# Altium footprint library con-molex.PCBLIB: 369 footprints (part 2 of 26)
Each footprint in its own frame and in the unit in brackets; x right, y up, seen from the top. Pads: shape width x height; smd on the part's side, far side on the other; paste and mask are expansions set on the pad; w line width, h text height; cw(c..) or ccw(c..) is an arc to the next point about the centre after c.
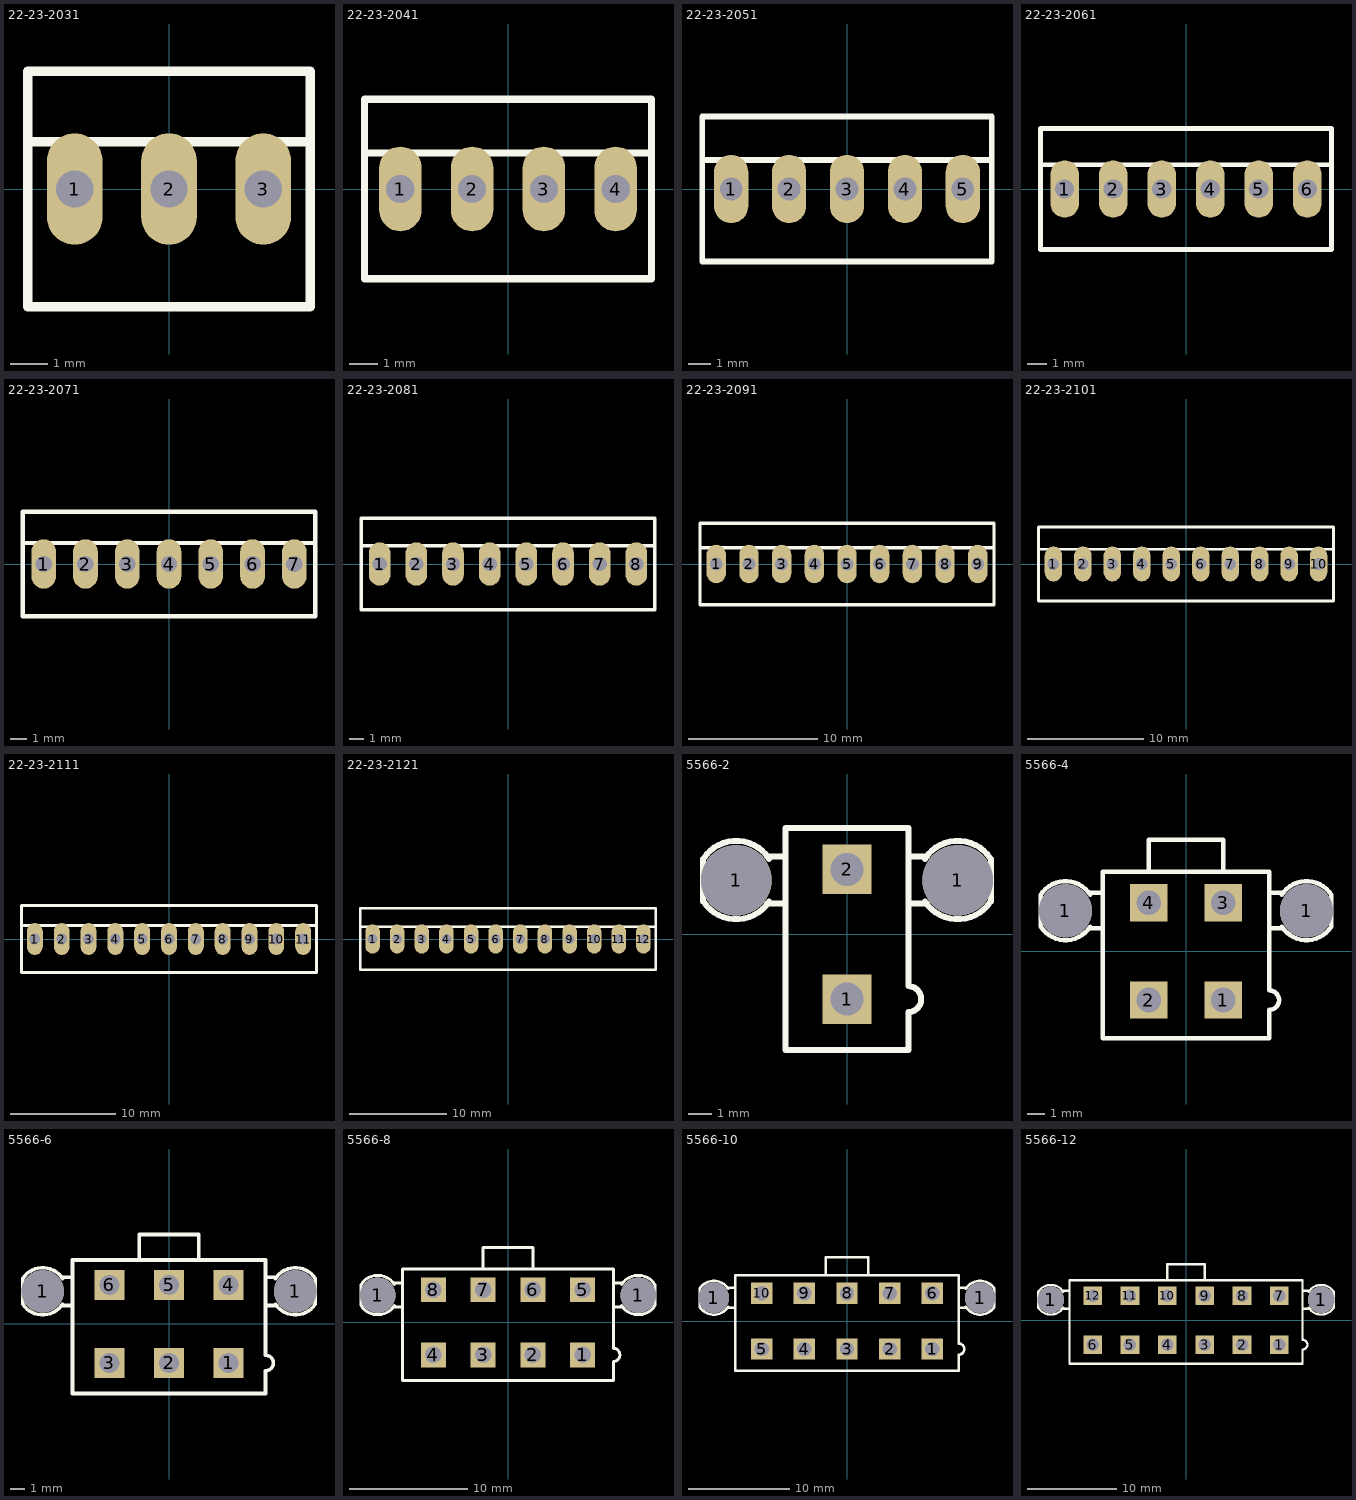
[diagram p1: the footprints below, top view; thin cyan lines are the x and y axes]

## 22-23-2031 [mm]
pads (3):
  oval 1.5x3 hole 1: 1(-2.54,0) 2(0,0) 3(2.54,0)
Top Overlay:
  lines w0.254: -3.81,1.27 -3.81,-3.175 3.81,-3.175 3.81,1.27 ; -3.81,1.27 -3.81,3.175 3.81,3.175 3.81,1.27 ; -3.81,1.27 3.81,1.27

## 22-23-2041 [mm]
pads (4):
  oval 1.5x3 hole 1: 1(-3.81,0) 2(-1.27,0) 3(1.27,0) 4(3.81,0)
Top Overlay:
  lines w0.254: -5.08,1.27 -5.08,-3.175 5.08,-3.175 5.08,1.27 ; -5.08,1.27 -5.08,3.175 5.08,3.175 5.08,1.27 ; -5.08,1.27 5.08,1.27

## 22-23-2051 [mm]
pads (5):
  oval 1.5x3 hole 1: 1(-5.08,0) 2(-2.54,0) 3(0,0) 4(2.54,0) 5(5.08,0)
Top Overlay:
  lines w0.254: -6.35,1.27 -6.35,-3.175 6.35,-3.175 6.35,1.27 ; -6.35,1.27 -6.35,3.175 6.35,3.175 6.35,1.27 ; -6.35,1.27 6.35,1.27

## 22-23-2061 [mm]
pads (6):
  oval 1.5x3 hole 1: 1(-6.35,0) 2(-3.81,0) 3(-1.27,0) 4(1.27,0) 5(3.81,0) 6(6.35,0)
Top Overlay:
  lines w0.254: -7.62,1.27 -7.62,-3.175 7.62,-3.175 7.62,1.27 ; -7.62,1.27 -7.62,3.175 7.62,3.175 7.62,1.27 ; -7.62,1.27 7.62,1.27

## 22-23-2071 [mm]
pads (7):
  oval 1.5x3 hole 1: 1(-7.62,0) 2(-5.08,0) 3(-2.54,0) 4(0,0) 5(2.54,0) 6(5.08,0) 7(7.62,0)
Top Overlay:
  lines w0.254: -8.89,1.27 -8.89,-3.175 8.89,-3.175 8.89,1.27 ; -8.89,1.27 -8.89,3.175 8.89,3.175 8.89,1.27 ; -8.89,1.27 8.89,1.27

## 22-23-2081 [mm]
pads (8):
  oval 1.5x3 hole 1: 1(-8.89,0) 2(-6.35,0) 3(-3.81,0) 4(-1.27,0) 5(1.27,0) 6(3.81,0) 7(6.35,0) 8(8.89,0)
Top Overlay:
  lines w0.254: -10.16,1.27 -10.16,-3.175 10.16,-3.175 10.16,1.27 ; -10.16,1.27 -10.16,3.175 10.16,3.175 10.16,1.27 ; -10.16,1.27 10.16,1.27

## 22-23-2091 [mm]
pads (9):
  oval 1.5x3 hole 1: 1(-10.16,0) 2(-7.62,0) 3(-5.08,0) 4(-2.54,0) 5(0,0) 6(2.54,0) 7(5.08,0) 8(7.62,0) 9(10.16,0)
Top Overlay:
  lines w0.254: -11.43,1.27 -11.43,-3.175 11.43,-3.175 11.43,1.27 ; -11.43,1.27 -11.43,3.175 11.43,3.175 11.43,1.27 ; -11.43,1.27 11.43,1.27

## 22-23-2101 [mm]
pads (10):
  oval 1.5x3 hole 1: 1(-11.43,0) 2(-8.89,0) 3(-6.35,0) 4(-3.81,0) 5(-1.27,0) 6(1.27,0) 7(3.81,0) 8(6.35,0) 9(8.89,0) 10(11.43,0)
Top Overlay:
  lines w0.254: -12.7,1.27 -12.7,-3.175 12.7,-3.175 12.7,1.27 ; -12.7,1.27 -12.7,3.175 12.7,3.175 12.7,1.27 ; -12.7,1.27 12.7,1.27

## 22-23-2111 [mm]
pads (11):
  oval 1.5x3 hole 1: 1(-12.7,0) 2(-10.16,0) 3(-7.62,0) 4(-5.08,0) 5(-2.54,0) 6(0,0) 7(2.54,0) 8(5.08,0) 9(7.62,0) 10(10.16,0) 11(12.7,0)
Top Overlay:
  lines w0.254: -13.97,1.27 -13.97,-3.175 13.97,-3.175 13.97,1.27 ; -13.97,1.27 -13.97,3.175 13.97,3.175 13.97,1.27 ; -13.97,1.27 13.97,1.27

## 22-23-2121 [mm]
pads (12):
  oval 1.5x3 hole 1: 1(-13.97,0) 2(-11.43,0) 3(-8.89,0) 4(-6.35,0) 5(-3.81,0) 6(-1.27,0) 7(1.27,0) 8(3.81,0) 9(6.35,0) 10(8.89,0) 11(11.43,0) 12(13.97,0)
Top Overlay:
  lines w0.254: -15.24,1.27 -15.24,-3.175 15.24,-3.175 15.24,1.27 ; -15.24,1.27 -15.24,3.175 15.24,3.175 15.24,1.27 ; -15.24,1.27 15.24,1.27

## 5566-2 [mm]
pads (4):
  round 3 hole 3: 1(-4.7,2.29) 1(4.7,2.29)
  rect 2.1x2.1 hole 1.4: 1(0,-2.75) 2(0,2.75)
Top Overlay:
  lines w0.254: -3.4,1.3 -2.7,1.3 ; -3.4,3.3 -2.7,3.3 ; -3.3,1.4 cw(c-4.7,2.3) -6.1,1.4 -6.1,3.2 cw(c-4.7,2.3) -3.3,3.2 ; 2.7,1.3 3.4,1.3 ; 2.7,3.3 3.4,3.3 ; 3.3,1.4 ccw(c4.7,2.3) 6.1,1.4 6.1,3.2 ccw(c4.7,2.3) 3.3,3.2 ; -2.6,-4.9 -2.6,4.5 2.6,4.5 2.6,-2.2 cw(c2.6,-2.75) 2.6,-3.3 2.6,-4.9 -2.6,-4.9

## 5566-4 [mm]
pads (6):
  round 3 hole 3: 1(-6.8,2.29) 1(6.8,2.29)
  rect 2.1x2.1 hole 1.4: 1(2.1,-2.75) 2(-2.1,-2.75) 3(2.1,2.75) 4(-2.1,2.75)
Top Overlay:
  lines w0.254: -5.5,1.3 -4.8,1.3 ; -5.5,3.3 -4.8,3.3 ; -5.4,1.4 cw(c-6.8,2.3) -8.2,1.4 -8.2,3.2 cw(c-6.8,2.3) -5.4,3.2 ; -2.1,4.6 -2.1,6.3 2.1,6.3 2.1,4.6 ; 4.8,1.3 5.5,1.3 ; 4.8,3.3 5.5,3.3 ; 5.4,1.4 ccw(c6.8,2.3) 8.2,1.4 8.2,3.2 ccw(c6.8,2.3) 5.4,3.2 ; -4.7,-4.9 4.7,-4.9 4.7,-3.3 ccw(c4.7,-2.75) 4.7,-2.2 4.7,4.5 -4.7,4.5 -4.7,-4.9

## 5566-6 [mm]
pads (8):
  round 3 hole 3: 1(-8.9,2.29) 1(8.9,2.29)
  rect 2.1x2.1 hole 1.4: 1(4.2,-2.75) 2(0,-2.75) 3(-4.2,-2.75) 4(4.2,2.75) 5(0,2.75) 6(-4.2,2.75)
Top Overlay:
  lines w0.254: -7.6,1.3 -6.9,1.3 ; -7.6,3.3 -6.9,3.3 ; -7.5,1.4 cw(c-8.9,2.3) -10.3,1.4 -10.3,3.2 cw(c-8.9,2.3) -7.5,3.2 ; -2.1,4.6 -2.1,6.3 2.1,6.3 2.1,4.6 ; 6.9,1.3 7.6,1.3 ; 6.9,3.3 7.6,3.3 ; 7.5,1.4 ccw(c8.9,2.3) 10.3,1.4 10.3,3.2 ccw(c8.9,2.3) 7.5,3.2 ; -6.8,-4.9 6.8,-4.9 6.8,-3.3 ccw(c6.8,-2.75) 6.8,-2.2 6.8,4.5 -6.8,4.5 -6.8,-4.9

## 5566-8 [mm]
pads (10):
  round 3 hole 3: 1(-11,2.29) 1(11,2.29)
  rect 2.1x2.1 hole 1.4: 1(6.3,-2.75) 2(2.1,-2.75) 3(-2.1,-2.75) 4(-6.3,-2.75) 5(6.3,2.75) 6(2.1,2.75) 7(-2.1,2.75) 8(-6.3,2.75)
Top Overlay:
  lines w0.254: -9.7,1.3 -9,1.3 ; -9.7,3.3 -9,3.3 ; -9.6,1.4 cw(c-11,2.3) -12.4,1.4 -12.4,3.2 cw(c-11,2.3) -9.6,3.2 ; -2.1,4.6 -2.1,6.3 2.1,6.3 2.1,4.6 ; 9,1.3 9.7,1.3 ; 9,3.3 9.7,3.3 ; 9.6,1.4 ccw(c11,2.3) 12.4,1.4 12.4,3.2 ccw(c11,2.3) 9.6,3.2 ; -8.9,-4.9 8.9,-4.9 8.9,-3.3 ccw(c8.9,-2.75) 8.9,-2.2 8.9,4.5 -8.9,4.5 -8.9,-4.9

## 5566-10 [mm]
pads (12):
  round 3 hole 3: 1(-13.1,2.29) 1(13.1,2.29)
  rect 2.1x2.1 hole 1.4: 1(8.4,-2.75) 2(4.2,-2.75) 3(0,-2.75) 4(-4.2,-2.75) 5(-8.4,-2.75) 6(8.4,2.75) 7(4.2,2.75) 8(0,2.75) 9(-4.2,2.75) 10(-8.4,2.75)
Top Overlay:
  lines w0.254: -11.8,1.3 -11.1,1.3 ; -11.8,3.3 -11.1,3.3 ; -11.7,1.4 cw(c-13.1,2.3) -14.5,1.4 -14.5,3.2 cw(c-13.1,2.3) -11.7,3.2 ; -2.1,4.6 -2.1,6.3 2.1,6.3 2.1,4.6 ; 11.1,1.3 11.8,1.3 ; 11.1,3.3 11.8,3.3 ; 11.7,1.4 ccw(c13.1,2.3) 14.5,1.4 14.5,3.2 ccw(c13.1,2.3) 11.7,3.2 ; -11,-4.9 11,-4.9 11,-3.3 ccw(c11,-2.75) 11,-2.2 11,4.5 -11,4.5 -11,-4.9

## 5566-12 [mm]
pads (14):
  round 3 hole 3: 1(-15.2,2.29) 1(15.2,2.29)
  rect 2.1x2.1 hole 1.4: 1(10.5,-2.75) 2(6.3,-2.75) 3(2.1,-2.75) 4(-2.1,-2.75) 5(-6.3,-2.75) 6(-10.5,-2.75) 7(10.5,2.75) 8(6.3,2.75) 9(2.1,2.75) 10(-2.1,2.75) 11(-6.3,2.75) 12(-10.5,2.75)
Top Overlay:
  lines w0.254: -13.9,1.3 -13.2,1.3 ; -13.9,3.3 -13.2,3.3 ; -13.8,1.4 cw(c-15.2,2.3) -16.6,1.4 -16.6,3.2 cw(c-15.2,2.3) -13.8,3.2 ; -2.1,4.6 -2.1,6.3 2.1,6.3 2.1,4.6 ; 13.2,1.3 13.9,1.3 ; 13.2,3.3 13.9,3.3 ; 13.8,1.4 ccw(c15.2,2.3) 16.6,1.4 16.6,3.2 ccw(c15.2,2.3) 13.8,3.2 ; -13.1,-4.9 13.1,-4.9 13.1,-3.3 ccw(c13.1,-2.75) 13.1,-2.2 13.1,4.5 -13.1,4.5 -13.1,-4.9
